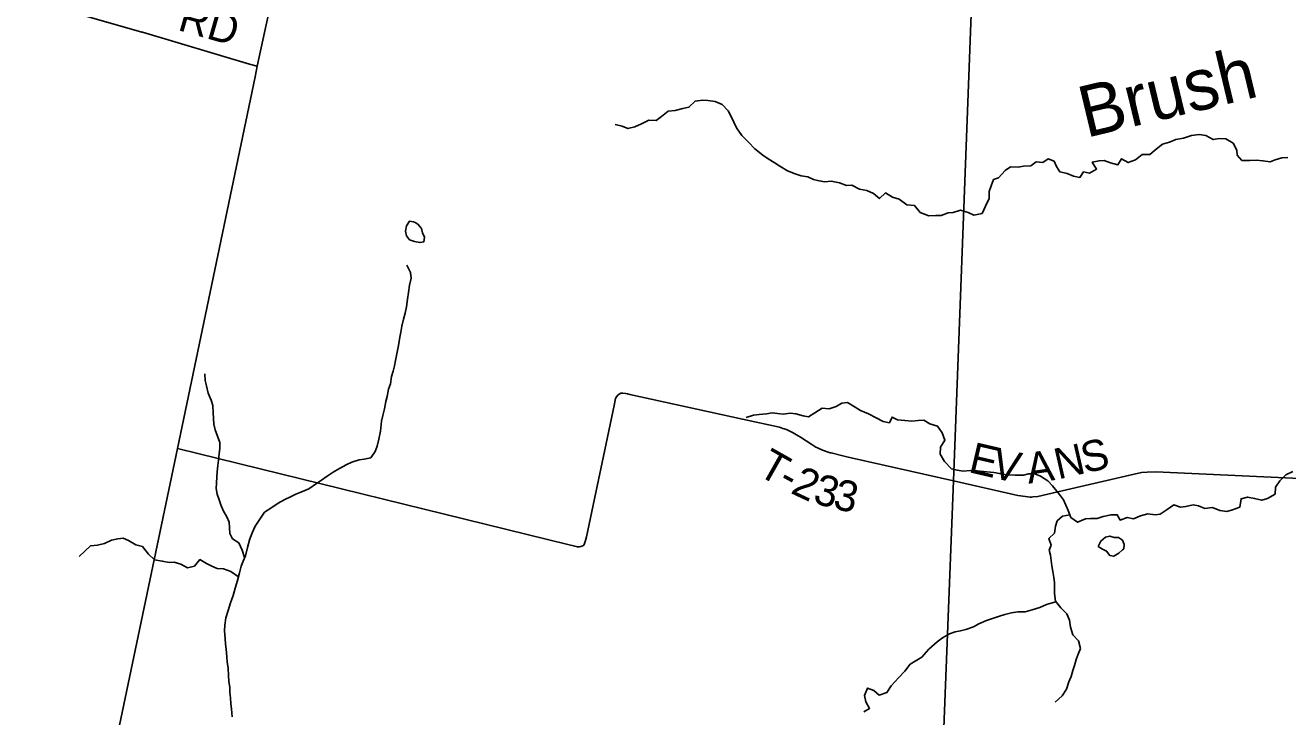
# Model space of a CAD drawing. Extents: x 0 to 34, y 0 to 22.
# Drawn here: x 4.289 to 5.454, y 16.767 to 17.405 of the extents above; entities that cross this region are included whole.
import ezdxf

# ---------------------------------------------------------------- set-up
doc = ezdxf.new("R2010")
doc.units = 0
for name, color, linetype in [('GM_X_County_Road', 7, 'Continuous'), ('GM_X_Minor_Lake', 7, 'Continuous'), ('GM_X_Minor_River', 7, 'Continuous'), ('GM_X_Minor_River_Text', 7, 'Continuous'), ('GM_X_State_Route', 7, 'Continuous'), ('GM_X_Township_Road', 7, 'Continuous'), ('GM_X_Township_Road_Text', 7, 'Continuous')]:
    doc.layers.add(name, color=color, linetype=linetype)

msp = doc.modelspace()

# ---------------------------------------------------------------- linework, layer by layer
at = {"layer": 'GM_X_County_Road'}
for points in [[(4.5014, 17.3574), (4.5033, 17.3673), (4.6179, 17.894)], [(4.2936, 16.3773), (4.333, 16.5543), (4.4295, 17.0147), (4.5014, 17.3574)]]:
    msp.add_lwpolyline(points, dxfattribs=at)
at = {"layer": 'GM_X_Minor_Lake'}
for points in [[(4.6489, 17.2231), (4.6475, 17.2238), (4.6437, 17.2244), (4.641, 17.2201), (4.6402, 17.2153), (4.641, 17.211), (4.6438, 17.2072)], [(4.6438, 17.2072), (4.6485, 17.2056), (4.6533, 17.2047), (4.6571, 17.2054), (4.6575, 17.2096), (4.6558, 17.2136), (4.6547, 17.2178), (4.6516, 17.2216), (4.6489, 17.2231)], [(5.3018, 16.9213), (5.3031, 16.9224), (5.3034, 16.9264), (5.3019, 16.9303), (5.298, 16.9326), (5.294, 16.9326), (5.29, 16.934), (5.2862, 16.9331), (5.2819, 16.9295), (5.2794, 16.9245)], [(5.2794, 16.9245), (5.2832, 16.9221), (5.2871, 16.9202), (5.29, 16.9162), (5.2937, 16.9154), (5.2985, 16.9184), (5.3018, 16.9213)]]:
    msp.add_lwpolyline(points, dxfattribs=at)
at = {"layer": 'GM_X_Minor_River'}
for points in [[(5.3655, 17.3034), (5.358, 17.3011), (5.3511, 17.2996), (5.3451, 17.2974), (5.3388, 17.2953), (5.3329, 17.2908), (5.327, 17.2859), (5.3198, 17.2859), (5.3137, 17.281), (5.3071, 17.2784), (5.3009, 17.282), (5.2976, 17.2763), (5.2906, 17.2782), (5.2849, 17.2803), (5.2802, 17.2802), (5.2739, 17.2789), (5.2779, 17.2724), (5.2713, 17.2688), (5.2658, 17.2698), (5.2625, 17.2647), (5.2567, 17.266), (5.2508, 17.2685), (5.244, 17.2698), (5.241, 17.2748), (5.2387, 17.2797), (5.2332, 17.2818), (5.2283, 17.2784), (5.2222, 17.279), (5.2173, 17.2756), (5.2105, 17.2753), (5.2054, 17.2743), (5.1983, 17.2744), (5.1936, 17.2712), (5.1875, 17.2645), (5.1828, 17.2627), (5.1807, 17.257), (5.1788, 17.2517), (5.1787, 17.2452), (5.1753, 17.2382), (5.1722, 17.2314), (5.1645, 17.2299), (5.1592, 17.2324), (5.1522, 17.2345), (5.1455, 17.2323), (5.1408, 17.2321), (5.1343, 17.2296), (5.1296, 17.2297), (5.123, 17.2293), (5.1152, 17.2324), (5.1097, 17.2388), (5.1026, 17.2394), (5.0958, 17.2446), (5.0895, 17.2465), (5.0831, 17.2505), (5.0774, 17.2452), (5.0721, 17.2498), (5.0657, 17.2527), (5.059, 17.2538), (5.0519, 17.2576), (5.0471, 17.2573), (5.0405, 17.2598), (5.0329, 17.2613), (5.0271, 17.2608), (5.0218, 17.2615), (5.0166, 17.2629), (5.0115, 17.2652), (5.0053, 17.2661), (4.9996, 17.2681), (4.9926, 17.2709), (4.9854, 17.2751), (4.9803, 17.2784), (4.9747, 17.282), (4.9698, 17.2852), (4.9626, 17.291), (4.9567, 17.2974), (4.9505, 17.3035), (4.9456, 17.3104), (4.943, 17.3157), (4.9407, 17.321), (4.9379, 17.3261), (4.9324, 17.332), (4.9258, 17.3347), (4.9192, 17.3357), (4.9141, 17.3359), (4.9074, 17.3352), (4.9017, 17.3295), (4.8959, 17.3282), (4.889, 17.3265), (4.8826, 17.3258), (4.8763, 17.3209), (4.8714, 17.3173), (4.8646, 17.3175), (4.8579, 17.3141), (4.8516, 17.3115), (4.8454, 17.3098), (4.8399, 17.3121), (4.8335, 17.3136)], [(5.4545, 17.2832), (5.4488, 17.2828), (5.4427, 17.281), (5.438, 17.2791), (5.4314, 17.2802), (5.4255, 17.2806), (5.4194, 17.2803), (5.412, 17.2803), (5.4077, 17.2852), (5.4072, 17.29), (5.4038, 17.2964), (5.3973, 17.3003), (5.3911, 17.3007), (5.3856, 17.2997), (5.3788, 17.3035), (5.3726, 17.3045), (5.3655, 17.3034)], [(4.4811, 16.8791), (4.4829, 16.8861), (4.485, 16.8931), (4.4869, 16.9003), (4.4884, 16.9062), (4.4902, 16.9109), (4.4923, 16.9158), (4.4942, 16.9234), (4.4963, 16.9314), (4.499, 16.9378), (4.5013, 16.9431), (4.5055, 16.9497), (4.51, 16.956), (4.5159, 16.9598), (4.5226, 16.9643), (4.5288, 16.9679), (4.534, 16.9701), (4.5389, 16.9728), (4.5436, 16.9746), (4.5507, 16.9776), (4.5579, 16.9824), (4.5626, 16.9856), (4.5679, 16.9893), (4.5733, 16.9929), (4.5786, 16.9959), (4.5858, 16.9999), (4.5905, 17.0022), (4.5972, 17.0042), (4.6019, 17.005), (4.608, 17.0063), (4.6122, 17.0121), (4.6139, 17.017), (4.6156, 17.0233), (4.617, 17.0309), (4.618, 17.04), (4.6191, 17.0451), (4.6207, 17.0514), (4.622, 17.058), (4.623, 17.0629), (4.6245, 17.0694), (4.6261, 17.0745), (4.6272, 17.0811), (4.6286, 17.0862), (4.6299, 17.0911), (4.6309, 17.0961), (4.632, 17.1021), (4.6336, 17.1097), (4.6349, 17.1175), (4.6359, 17.1222), (4.6367, 17.1275), (4.6382, 17.1342), (4.6398, 17.1397), (4.6409, 17.1453), (4.6419, 17.1526), (4.6429, 17.1586), (4.6438, 17.1653), (4.6452, 17.1719), (4.6448, 17.177), (4.6413, 17.1839)], [(4.4916, 16.9143), (4.4893, 16.9212), (4.4864, 16.9278), (4.4804, 16.9316), (4.4779, 16.9364), (4.4776, 16.9421), (4.4772, 16.947), (4.4752, 16.9518), (4.4718, 16.9576), (4.4697, 16.9628), (4.468, 16.9675), (4.4662, 16.9726), (4.4654, 16.9778), (4.4656, 16.9829), (4.466, 16.9886), (4.4662, 16.9933), (4.4668, 16.999), (4.4676, 17.0041), (4.4682, 17.0098), (4.4686, 17.0151), (4.4686, 17.0204), (4.4667, 17.0261), (4.4643, 17.032), (4.4632, 17.0373), (4.4628, 17.0425), (4.4627, 17.0476), (4.4623, 17.0544), (4.4606, 17.0593), (4.4578, 17.0658), (4.4565, 17.0726), (4.4552, 17.0774), (4.455, 17.0835)], [(5.226, 16.9894), (5.2209, 16.9913), (5.2151, 16.9915), (5.2103, 16.9902), (5.2027, 16.9901), (5.1948, 16.9905), (5.1882, 16.9916), (5.1829, 16.9926), (5.1734, 16.9936), (5.1677, 16.9943), (5.1611, 16.9946), (5.1546, 16.994), (5.1491, 16.9948), (5.144, 16.9959), (5.1376, 17.0028), (5.1335, 17.0096), (5.1337, 17.0161), (5.1379, 17.0225), (5.1353, 17.0292), (5.1311, 17.0353), (5.1241, 17.0377), (5.1184, 17.041), (5.1131, 17.0406), (5.1073, 17.0401), (5.1008, 17.0407), (5.094, 17.0413), (5.0891, 17.0437), (5.0866, 17.0386), (5.0809, 17.0396), (5.0743, 17.0432), (5.0673, 17.0469), (5.0601, 17.0499), (5.055, 17.0528), (5.048, 17.0572), (5.0429, 17.0566), (5.0374, 17.0536), (5.031, 17.0514), (5.0247, 17.0519), (5.0177, 17.0476), (5.012, 17.044), (5.0071, 17.0448), (5.0003, 17.0469), (4.9951, 17.0473), (4.9887, 17.0466), (4.9834, 17.0472), (4.9785, 17.0476), (4.9732, 17.0468), (4.9664, 17.0463), (4.9612, 17.0455), (4.9546, 17.0435)], [(5.4589, 16.9937), (5.4524, 16.9904), (5.4471, 16.9849), (5.4431, 16.9792), (5.4427, 16.9727), (5.4356, 16.9686), (5.4303, 16.9671), (5.4237, 16.9688), (5.4173, 16.97), (5.4112, 16.9685), (5.41, 16.9607), (5.4034, 16.9581), (5.3981, 16.9568), (5.3915, 16.9577), (5.3847, 16.9604), (5.3778, 16.9595), (5.372, 16.9618), (5.3669, 16.9628), (5.3602, 16.9614), (5.3553, 16.9607), (5.3492, 16.9628), (5.343, 16.9587), (5.3365, 16.9543), (5.3318, 16.9536), (5.3252, 16.9545), (5.3185, 16.9527), (5.3119, 16.95), (5.3062, 16.9512), (5.2997, 16.9488), (5.2969, 16.9537), (5.2912, 16.9537), (5.284, 16.9522), (5.2785, 16.9502), (5.2723, 16.9504), (5.2675, 16.95), (5.2603, 16.9468), (5.2541, 16.9512), (5.2515, 16.9575), (5.2496, 16.9626), (5.2473, 16.9675), (5.2436, 16.9723), (5.2372, 16.9803), (5.2328, 16.985), (5.226, 16.9894)], [(5.2532, 16.9535), (5.2463, 16.9525), (5.2416, 16.948), (5.2401, 16.9433), (5.2389, 16.9368), (5.2338, 16.9319), (5.2358, 16.9258), (5.2341, 16.9211), (5.2354, 16.9163), (5.236, 16.9114), (5.2367, 16.9065), (5.2376, 16.9015), (5.2385, 16.8959), (5.2389, 16.8911), (5.2391, 16.8862), (5.2389, 16.8811), (5.2398, 16.8739), (5.2449, 16.868), (5.2505, 16.8624), (5.253, 16.8564), (5.2537, 16.8501), (5.2558, 16.8431), (5.2612, 16.8374), (5.2629, 16.8303), (5.261, 16.8252), (5.2591, 16.8203), (5.2574, 16.8148), (5.256, 16.8101), (5.2543, 16.8046), (5.2522, 16.7995), (5.2501, 16.7928), (5.2461, 16.7866), (5.2396, 16.7809)], [(4.4859, 16.8964), (4.4789, 16.9013), (4.4721, 16.9038), (4.4663, 16.9042), (4.4613, 16.9063), (4.4564, 16.9088), (4.4504, 16.9124), (4.4452, 16.9063), (4.4388, 16.9049), (4.4326, 16.9081), (4.4265, 16.91), (4.4218, 16.9097), (4.4155, 16.911), (4.4083, 16.9122), (4.403, 16.9175), (4.3972, 16.9244), (4.3911, 16.9261), (4.3843, 16.9301), (4.3794, 16.932), (4.3747, 16.9315), (4.3688, 16.9303), (4.3624, 16.9273), (4.3559, 16.9258), (4.3495, 16.9251), (4.3443, 16.9204), (4.339, 16.9151)], [(4.4801, 16.7674), (4.4796, 16.7746), (4.479, 16.7793), (4.4785, 16.7848), (4.4779, 16.7898), (4.4778, 16.7945), (4.477, 16.8004), (4.4767, 16.8053), (4.4763, 16.8125), (4.4756, 16.8177), (4.4752, 16.8226), (4.4745, 16.8298), (4.4738, 16.8345), (4.4736, 16.8395), (4.4731, 16.8467), (4.4733, 16.852), (4.4744, 16.8588), (4.4765, 16.8653), (4.4786, 16.8726), (4.4811, 16.8791)], [(5.2403, 16.8733), (5.2316, 16.8708), (5.2254, 16.8682), (5.2183, 16.866), (5.2119, 16.8643), (5.2051, 16.8641), (5.1992, 16.8632), (5.1933, 16.8617), (5.1882, 16.8602), (5.1818, 16.8581), (5.1763, 16.8562), (5.1692, 16.8532), (5.1643, 16.8504), (5.1573, 16.8478), (5.1524, 16.8467), (5.1474, 16.8457), (5.1421, 16.844), (5.1358, 16.8401), (5.1307, 16.8365), (5.1229, 16.8297), (5.1166, 16.8225), (5.1119, 16.8195), (5.1058, 16.8159), (5.1009, 16.8095), (5.095, 16.8032), (5.0883, 16.7961), (5.0843, 16.7898), (5.0773, 16.7874), (5.0724, 16.7916), (5.0663, 16.7939), (5.0637, 16.7869), (5.0648, 16.7812), (5.0683, 16.7751), (5.0632, 16.7721)]]:
    msp.add_lwpolyline(points, dxfattribs=at)
at = {"layer": 'GM_X_State_Route'}
for points in [[(5.1459, 16.9851), (5.1759, 17.7808), (5.1767, 17.7957), (5.1854, 18.0568), (5.1893, 18.1658), (5.2003, 18.4901), (5.2066, 18.668)], [(4.9877, 16.2084), (5.0033, 16.2754), (5.0119, 16.3131), (5.016, 16.3308), (5.02, 16.3446), (5.1277, 16.6254), (5.1298, 16.6339), (5.1314, 16.6405), (5.1326, 16.649), (5.133, 16.6551), (5.1459, 16.9851)]]:
    msp.add_lwpolyline(points, dxfattribs=at)
at = {"layer": 'GM_X_Township_Road'}
for points in [[(4.1657, 17.4652), (4.3967, 17.3988), (4.3972, 17.3986)], [(4.3972, 17.3986), (4.4962, 17.3692), (4.5033, 17.3673)], [(4.4295, 17.0147), (4.7899, 16.9262), (4.7962, 16.9246), (4.7987, 16.9241), (4.8004, 16.9241), (4.8018, 16.9244), (4.8038, 16.9252), (4.8045, 16.9258), (4.8054, 16.9272), (4.8063, 16.9299), (4.807, 16.9333), (4.8326, 17.0546), (4.834, 17.0608), (4.8347, 17.0625), (4.8361, 17.0641), (4.8373, 17.065), (4.8389, 17.0657), (4.8407, 17.0659), (4.8432, 17.0656), (4.845, 17.0652), (4.8471, 17.0647), (4.951, 17.0418), (4.9851, 17.0344), (4.9883, 17.0333)], [(4.9883, 17.0333), (4.9916, 17.0323), (4.9978, 17.0294), (5.0024, 17.0266)], [(5.0024, 17.0266), (5.0045, 17.0253), (5.0151, 17.0184), (5.0189, 17.0161)], [(5.0189, 17.0161), (5.0202, 17.0153), (5.0248, 17.0133), (5.032, 17.0109), (5.033, 17.0107)], [(5.033, 17.0107), (5.0425, 17.0083), (5.0448, 17.0078), (5.0474, 17.0072), (5.0513, 17.0063), (5.1459, 16.9851)], [(5.2191, 16.9701), (5.2235, 16.9706), (5.2421, 16.9748), (5.3126, 16.9912), (5.3194, 16.9926), (5.3244, 16.9931), (5.3326, 16.9933), (5.6315, 16.9795)], [(5.1459, 16.9851), (5.2052, 16.9716), (5.2124, 16.9704), (5.2167, 16.97)], [(5.2167, 16.97), (5.2177, 16.9699), (5.2191, 16.9701)]]:
    msp.add_lwpolyline(points, dxfattribs=at)

# ---------------------------------------------------------------- texts
at = {"layer": 'GM_X_Minor_River_Text'}
msp.add_text('Brush', height=0.04735, rotation=13.4874, dxfattribs=at).set_placement((5.2681, 17.3011))
at = {"layer": 'GM_X_Township_Road_Text'}
for s, height, rotation, p in [('RD', 0.02841, 344.0556, (4.4288, 17.4009)), ('S', 0.0284, 12.6705, (5.2668, 16.9918)), ('T', 0.0284, 330.5321, (4.9637, 16.9912)), ('E', 0.0284, 346.945, (5.1587, 16.9932)), ('V', 0.0284, 347.1861, (5.1795, 16.9883)), ('A', 0.0284, 7.8422, (5.215, 16.9823)), ('N', 0.0284, 12.8619, (5.2424, 16.9862)), ('-', 0.0284, 331.495, (4.9826, 16.9805)), ('2', 0.0284, 334.9059, (4.9945, 16.9741)), ('3', 0.0284, 344.3183, (5.0151, 16.9649)), ('3', 0.0284, 347.4024, (5.0336, 16.9597))]:
    msp.add_text(s, height=height, rotation=rotation, dxfattribs=at).set_placement(p)

doc.saveas('drawing.dxf')
